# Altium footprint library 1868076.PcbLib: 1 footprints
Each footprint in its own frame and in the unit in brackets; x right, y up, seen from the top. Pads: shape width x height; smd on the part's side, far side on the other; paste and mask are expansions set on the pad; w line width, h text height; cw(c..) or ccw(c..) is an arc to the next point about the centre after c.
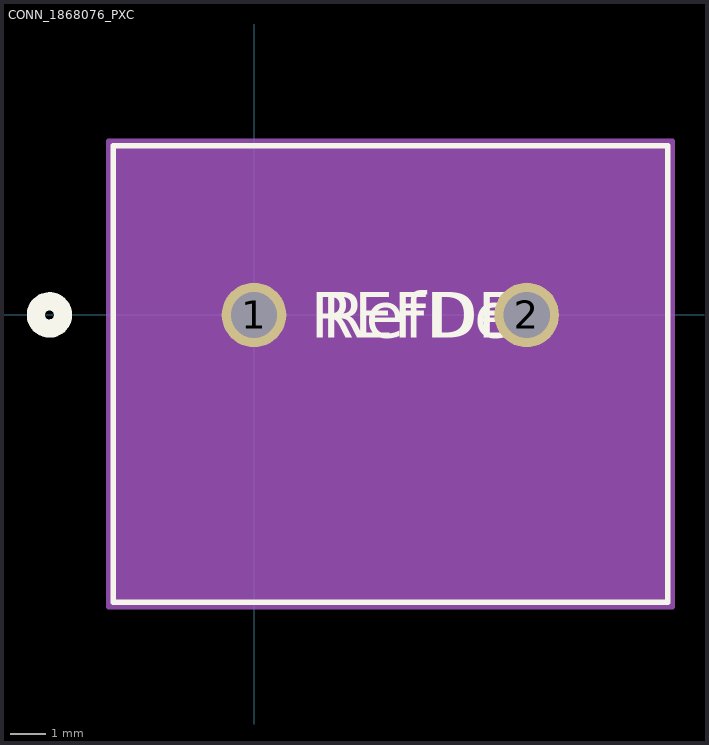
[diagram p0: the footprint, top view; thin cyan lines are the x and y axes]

## CONN_1868076_PXC [mil]
pads (2):
  round 71 / inner round 60 / far side round 71 hole 51 paste-35.5 mask+0: 1(0,0) 2(300,0)
Top Overlay:
  circle w20: c-225,0 r15
  lines w6: -155,-316.02 455,-316.02 455,186.1 -155,186.1 -155,-316.02
  text "RefDes" at 75,-25 h50
  text "REFDES" at 62.5,-25 h50
Bottom Overlay:
  circle w20: c-225,0 r15
Mechanical 13:
  circle w20: c0,75 r15
  lines w1: -150,-311.02 450,-311.02 450,181.1 -150,181.1 -150,-311.02
  text "RefDes2" at 62.5,-25 h50
Mechanical 15:
  region: 460,191.1 -160,191.1 -160,-321.02 460,-321.02
  lines w6: -160,-321.02 -160,191.1 460,191.1 460,-321.02 -160,-321.02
